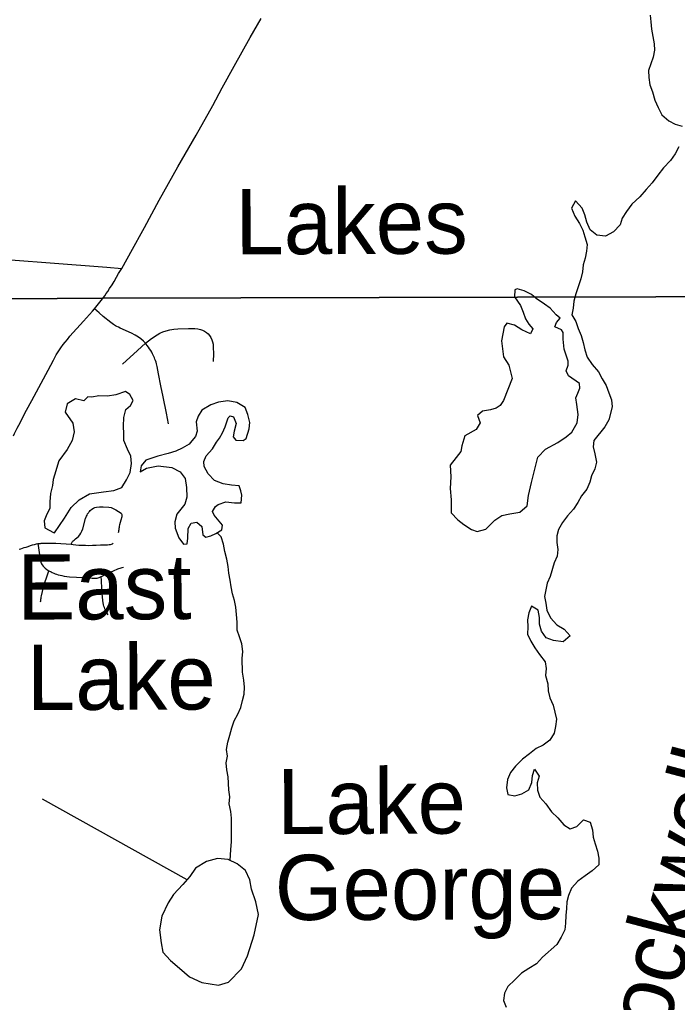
# Model space of a CAD drawing. Extents: x 0 to 34, y 0 to 22.
# Drawn here: x 3.606 to 4.562, y 16.187 to 17.616 of the extents above; entities that cross this region are included whole.
import ezdxf

# ---------------------------------------------------------------- set-up
doc = ezdxf.new("R2010")
doc.units = 0
for name, color, linetype in [('GM_X_City_Street', 7, 'Continuous'), ('GM_X_Corporation', 7, 'Continuous'), ('GM_X_County_Road', 7, 'Continuous'), ('GM_X_Major_Lake', 7, 'Continuous'), ('GM_X_Major_Lake_Text', 7, 'Continuous'), ('GM_X_Minor_Lake', 7, 'Continuous'), ('GM_X_Minor_Lake_Text', 7, 'Continuous'), ('GM_X_Minor_River', 7, 'Continuous'), ('GM_X_Township_Road', 7, 'Continuous')]:
    doc.layers.add(name, color=color, linetype=linetype)

msp = doc.modelspace()

# ---------------------------------------------------------------- linework, layer by layer
at = {"layer": 'GM_X_City_Street'}
msp.add_lwpolyline([(3.4853, 17.2733), (3.5792, 17.2674), (3.5989, 17.2659), (3.6499, 17.2621), (3.7323, 17.2558), (3.7541, 17.2539)], dxfattribs=at)
at = {"layer": 'GM_X_Corporation'}
for points in [[(2.114, 20.6173), (2.114, 17.2048), (2.159, 17.2055), (2.5952, 17.2097), (2.6493, 17.2102), (3.0597, 17.2067), (3.4848, 17.2088), (3.5941, 17.2097), (3.7259, 17.2107), (4.732, 17.2135)], [(4.732, 17.2135), (3.7259, 17.2107), (3.5941, 17.2097), (3.4848, 17.2088), (3.0597, 17.2067), (2.6493, 17.2102), (2.5952, 17.2097), (2.159, 17.2055), (2.114, 17.2048), (2.114, 13.8173), (5.0539, 13.8173)], [(3.5941, 17.2097), (3.7259, 17.2107), (4.732, 17.2135)]]:
    msp.add_lwpolyline(points, dxfattribs=at)
at = {"layer": 'GM_X_County_Road'}
for points in [[(3.7846, 17.3093), (3.787, 17.3137), (3.8087, 17.3535), (3.8221, 17.3773), (3.8358, 17.4017), (3.8626, 17.4479), (3.8864, 17.4908), (3.9002, 17.5165), (3.9176, 17.548), (3.941, 17.5897), (3.9567, 17.6173)], [(3.7541, 17.2539), (3.7698, 17.282), (3.7846, 17.3093)], [(3.7261, 17.2101), (3.7293, 17.2144), (3.7316, 17.2176), (3.7338, 17.2207), (3.7364, 17.2247), (3.7401, 17.2303), (3.743, 17.2352), (3.7466, 17.2412), (3.7496, 17.2466), (3.7541, 17.2539)], [(3.7144, 17.1954), (3.7185, 17.2003), (3.7224, 17.2051), (3.7261, 17.2101)], [(3.5966, 17.011), (3.5982, 17.0143), (3.6001, 17.018), (3.602, 17.0219), (3.6044, 17.0265), (3.6156, 17.048), (3.6233, 17.0622), (3.6301, 17.0748), (3.6469, 17.106), (3.6546, 17.1209), (3.6566, 17.1246), (3.6588, 17.1286), (3.6606, 17.1315), (3.6625, 17.1344), (3.6655, 17.1385), (3.6691, 17.1434), (3.6717, 17.1467), (3.6751, 17.151), (3.6786, 17.1555), (3.6985, 17.1774), (3.7116, 17.1921), (3.7144, 17.1954)]]:
    msp.add_lwpolyline(points, dxfattribs=at)
at = {"layer": 'GM_X_Major_Lake'}
for points in [[(4.5229, 17.6222), (4.5237, 17.6124), (4.5245, 17.6017), (4.5285, 17.5805), (4.5289, 17.5711), (4.5271, 17.5612), (4.5238, 17.5513), (4.5205, 17.5418), (4.5206, 17.5316), (4.5225, 17.5209), (4.526, 17.5107), (4.5295, 17.4986), (4.5345, 17.488), (4.5399, 17.4775), (4.5498, 17.4688), (4.5593, 17.464), (4.5692, 17.461)], [(4.5645, 17.4306), (4.5593, 17.4207), (4.5521, 17.4112), (4.542, 17.4001), (4.5341, 17.3898), (4.5259, 17.3784), (4.5169, 17.3688), (4.5079, 17.3581), (4.4962, 17.3474), (4.4884, 17.3367), (4.482, 17.3272), (4.4791, 17.3173), (4.4693, 17.3074), (4.4576, 17.3009), (4.4451, 17.3023), (4.4356, 17.3102), (4.4306, 17.3215), (4.4279, 17.3321), (4.4236, 17.3419), (4.4141, 17.3525), (4.4081, 17.3418), (4.4131, 17.3301), (4.42, 17.3195), (4.4246, 17.3097), (4.4277, 17.2999), (4.4309, 17.2889), (4.4302, 17.279), (4.4284, 17.2692), (4.4254, 17.2593), (4.4243, 17.249), (4.4218, 17.2388), (4.4185, 17.2289), (4.4144, 17.2171), (4.4118, 17.2065), (4.4108, 17.1962), (4.4089, 17.1867), (4.4147, 17.1769), (4.4182, 17.1667), (4.4224, 17.1565), (4.4252, 17.1466), (4.4279, 17.136), (4.431, 17.1251), (4.4383, 17.1145), (4.4474, 17.1036), (4.4528, 17.0938), (4.4589, 17.0839), (4.4624, 17.0734), (4.4667, 17.0632), (4.4675, 17.0529), (4.4624, 17.0339), (4.4568, 17.024), (4.441, 17.0042), (4.4396, 16.9947), (4.4423, 16.9845), (4.4447, 16.9727), (4.4421, 16.9628), (4.4373, 16.9529), (4.4351, 16.9434), (4.4306, 16.9332), (4.4227, 16.9236), (4.4175, 16.9141), (4.4111, 16.9042), (4.4025, 16.8947), (4.3954, 16.8847), (4.3894, 16.8748), (4.3869, 16.8653), (4.3869, 16.8559), (4.3885, 16.8456), (4.3875, 16.8361)], [(4.3875, 16.8361), (4.383, 16.8262), (4.3771, 16.8065), (4.373, 16.7966), (4.3708, 16.7871), (4.369, 16.7772), (4.371, 16.7674), (4.3726, 16.7572), (4.3779, 16.7462), (4.3871, 16.736), (4.3978, 16.73), (4.4062, 16.7199), (4.396, 16.7114)], [(4.396, 16.7114), (4.382, 16.7132), (4.3717, 16.7173), (4.3648, 16.7271), (4.3617, 16.737), (4.3617, 16.7468), (4.3597, 16.7574), (4.3502, 16.763), (4.3465, 16.7535), (4.3443, 16.7433), (4.3447, 16.733), (4.3445, 16.7224), (4.3491, 16.7126), (4.3548, 16.7028), (4.3617, 16.693), (4.3701, 16.6824), (4.3717, 16.6726), (4.3703, 16.6623), (4.3738, 16.6506), (4.3742, 16.6404), (4.377, 16.6298), (4.3816, 16.6192), (4.3843, 16.6094), (4.3867, 16.5988), (4.3852, 16.5885), (4.383, 16.5786), (4.3767, 16.5683), (4.3669, 16.5611), (4.3571, 16.5564), (4.3473, 16.5488), (4.3372, 16.5411), (4.327, 16.5308), (4.3195, 16.5213), (4.3151, 16.5114), (4.314, 16.4992), (4.3156, 16.4894), (4.3259, 16.4876), (4.3361, 16.4903), (4.3462, 16.4964), (4.3507, 16.5071), (4.3517, 16.517), (4.3547, 16.5265), (4.3612, 16.5163), (4.3583, 16.5064), (4.3587, 16.4958), (4.3622, 16.4856), (4.371, 16.4758), (4.379, 16.4641), (4.3886, 16.4554), (4.397, 16.4456), (4.4065, 16.4396), (4.4163, 16.4431), (4.426, 16.4527), (4.4355, 16.4493), (4.439, 16.4384), (4.4399, 16.4274), (4.4426, 16.4176), (4.4461, 16.4073), (4.4481, 16.3971), (4.4481, 16.3873), (4.4384, 16.3785), (4.4282, 16.3712), (4.4177, 16.3635), (4.4083, 16.3536), (4.4042, 16.3429), (4.4016, 16.3334), (4.4009, 16.3239), (4.4003, 16.3137), (4.3996, 16.3027), (4.3985, 16.2928), (4.3933, 16.2822), (4.387, 16.2715), (4.3659, 16.2531), (4.3573, 16.2432), (4.3464, 16.2367), (4.3358, 16.2298), (4.3261, 16.2202), (4.3159, 16.2107), (4.3111, 16.2008), (4.3093, 16.1901), (4.3131, 16.1803)]]:
    msp.add_lwpolyline(points, dxfattribs=at)
at = {"layer": 'GM_X_Minor_Lake'}
for p, q in [((4.3219, 17.0939), (4.3096, 17.0623)), ((3.8625, 17.0312), (3.8638, 17.0175)), ((3.6627, 16.9746), (3.6561, 16.9537)), ((3.8218, 16.332), (3.8125, 16.3129))]:
    msp.add_line(p, q, dxfattribs=at)
for points in [[(4.3096, 17.0623), (4.3048, 17.0551), (4.2987, 17.0508), (4.2904, 17.0485), (4.2791, 17.0465), (4.2716, 17.0404), (4.2754, 17.0298), (4.2695, 17.0199), (4.2533, 17.0107), (4.2488, 16.9962), (4.2474, 16.9879), (4.2406, 16.9795), (4.232, 16.9684), (4.2329, 16.9514), (4.2319, 16.9343), (4.2335, 16.918), (4.2333, 16.8987), (4.2432, 16.8889), (4.2516, 16.8821), (4.263, 16.8746), (4.271, 16.8716), (4.2835, 16.8752), (4.2966, 16.8881), (4.3068, 16.8951), (4.3185, 16.8974), (4.3332, 16.8998), (4.3437, 16.909), (4.3459, 16.9242), (4.3499, 16.9428), (4.3595, 16.9796), (4.3707, 16.9915), (4.3884, 17.0011), (4.4005, 17.0095), (4.4088, 17.0161), (4.4166, 17.0298), (4.418, 17.0419), (4.416, 17.0563), (4.4148, 17.0662), (4.4174, 17.0726), (4.4204, 17.0799), (4.4199, 17.0867), (4.404, 17.0979), (4.4005, 17.1051), (4.4035, 17.1135), (4.4034, 17.1192), (4.3976, 17.1369), (4.3963, 17.1513), (4.3963, 17.1608), (4.3936, 17.165), (4.3841, 17.1691), (4.3863, 17.1755), (4.3916, 17.182), (4.3862, 17.1865), (4.3771, 17.1963), (4.3691, 17.2023), (4.3569, 17.2106), (4.3501, 17.2162), (4.3394, 17.2214), (4.3292, 17.2244), (4.3258, 17.2229), (4.3255, 17.2126), (4.3343, 17.2002), (4.3381, 17.1903), (4.3412, 17.1809), (4.3462, 17.173), (4.3523, 17.1662), (4.3486, 17.1589), (4.3361, 17.1649), (4.3254, 17.1717), (4.3144, 17.1746), (4.3103, 17.1693), (4.3067, 17.1488), (4.3095, 17.1256), (4.3172, 17.1136), (4.3219, 17.0939)], [(3.6561, 16.9537), (3.6543, 16.9472), (3.6532, 16.9385), (3.6506, 16.9271), (3.6496, 16.915), (3.6493, 16.9055), (3.6444, 16.8945), (3.6415, 16.8872), (3.6423, 16.877), (3.6549, 16.8703), (3.6564, 16.8699), (3.671, 16.8913), (3.6803, 16.9065), (3.6923, 16.9176), (3.7074, 16.9264), (3.7278, 16.9292), (3.7426, 16.9312), (3.7543, 16.9359), (3.761, 16.9469), (3.7662, 16.9576), (3.7684, 16.9705), (3.7675, 16.9811), (3.7625, 16.9913), (3.7571, 17.0038), (3.7571, 17.0136), (3.7566, 17.025), (3.7572, 17.0375), (3.7602, 17.0489), (3.767, 17.0551), (3.7707, 17.0623), (3.7657, 17.071), (3.7596, 17.0751), (3.7456, 17.0704), (3.7332, 17.0685), (3.7207, 17.0687), (3.7105, 17.0668), (3.7048, 17.0675), (3.6988, 17.0617), (3.6866, 17.0647), (3.6746, 17.0574), (3.672, 17.0452), (3.6831, 17.0294), (3.6851, 17.0165), (3.6818, 17.004), (3.6747, 16.991), (3.6627, 16.9746)], [(3.8638, 17.0175), (3.8615, 17.0099), (3.8563, 17.0034), (3.8522, 16.9988), (3.842, 16.9931), (3.8326, 16.9884), (3.8216, 16.9853), (3.8065, 16.9814), (3.7891, 16.9752), (3.7824, 16.9672), (3.781, 16.9585), (3.79, 16.9638), (3.807, 16.967), (3.8271, 16.9649), (3.8389, 16.9585), (3.8465, 16.9487), (3.8485, 16.9359), (3.8486, 16.9218), (3.8457, 16.9116), (3.834, 16.8971), (3.8315, 16.8857), (3.8316, 16.8766), (3.8373, 16.8626), (3.8438, 16.8535), (3.8491, 16.8536), (3.8502, 16.8623), (3.8505, 16.8763), (3.855, 16.884), (3.8633, 16.8852), (3.8705, 16.8788), (3.8721, 16.867), (3.8763, 16.8633), (3.8835, 16.8656), (3.891, 16.8687), (3.8997, 16.8741), (3.9008, 16.8809), (3.8935, 16.8899), (3.8886, 16.8956), (3.8862, 16.9009), (3.8907, 16.9081), (3.8945, 16.9112), (3.9054, 16.9151), (3.9183, 16.9133), (3.9278, 16.9133), (3.9288, 16.9244), (3.9273, 16.9308), (3.9249, 16.938), (3.9139, 16.939), (3.9014, 16.9408), (3.8889, 16.946), (3.8798, 16.9554), (3.874, 16.9664), (3.8736, 16.9736), (3.8769, 16.9816), (3.8859, 16.9919), (3.8919, 17.0018), (3.8964, 17.0075), (3.9009, 17.0151), (3.9046, 17.0239), (3.909, 17.0368), (3.9116, 17.0399), (3.9166, 17.0384), (3.9204, 17.0289), (3.9175, 17.0176), (3.9164, 17.0092), (3.9202, 17.0043), (3.9305, 17.004), (3.935, 17.0071), (3.9394, 17.0211), (3.9405, 17.0302), (3.9377, 17.042), (3.9335, 17.0518), (3.9217, 17.0593), (3.9085, 17.0615), (3.8948, 17.0595), (3.8839, 17.056), (3.8707, 17.0483), (3.8655, 17.0395), (3.8625, 17.0312)], [(3.8125, 16.3129), (3.8092, 16.2928), (3.8113, 16.2739), (3.814, 16.2606), (3.8251, 16.2482), (3.8381, 16.2369), (3.8529, 16.2245), (3.8704, 16.2163), (3.8947, 16.2123), (3.9094, 16.2166), (3.9285, 16.2361), (3.9371, 16.2551), (3.9467, 16.2855), (3.9529, 16.3152), (3.949, 16.3337), (3.9428, 16.3519), (3.9404, 16.3655), (3.9342, 16.3791), (3.922, 16.3889), (3.9087, 16.3952), (3.8932, 16.3966), (3.8774, 16.3923), (3.8615, 16.3827), (3.8533, 16.3705), (3.8428, 16.3587), (3.8293, 16.3442), (3.8218, 16.332)]]:
    msp.add_lwpolyline(points, dxfattribs=at)
at = {"layer": 'GM_X_Minor_River'}
for points in [[(3.9117, 16.3938), (3.9128, 16.4096), (3.9138, 16.4207), (3.9137, 16.4343), (3.914, 16.4449), (3.914, 16.4552), (3.9127, 16.465), (3.9104, 16.476), (3.9114, 16.4862), (3.9098, 16.4965), (3.9089, 16.5154), (3.907, 16.5256), (3.9058, 16.5355), (3.9079, 16.545), (3.9067, 16.5548), (3.9082, 16.5655), (3.9111, 16.5757), (3.9141, 16.5864), (3.9174, 16.5966), (3.923, 16.6062), (3.9271, 16.616), (3.93, 16.6259), (3.9322, 16.6354), (3.9325, 16.6453), (3.9317, 16.6559), (3.9297, 16.6673), (3.9295, 16.687), (3.9302, 16.6972), (3.9286, 16.7086), (3.9255, 16.7188), (3.922, 16.7286), (3.9219, 16.74), (3.9211, 16.751), (3.9203, 16.7616), (3.9179, 16.7714), (3.9152, 16.7813), (3.9132, 16.7911), (3.912, 16.801), (3.91, 16.8112), (3.9088, 16.8211), (3.9068, 16.8317), (3.9041, 16.8426), (3.9021, 16.8532), (3.8986, 16.8638), (3.8927, 16.8697)], [(3.8491, 16.3657), (3.6386, 16.4826)]]:
    msp.add_lwpolyline(points, dxfattribs=at)
at = {"layer": 'GM_X_Township_Road'}
for points in [[(3.7885, 17.1453), (3.7875, 17.1463), (3.7857, 17.1482), (3.7819, 17.1516), (3.7784, 17.1543), (3.7736, 17.1573), (3.7685, 17.1599), (3.752, 17.1672), (3.7495, 17.1685), (3.7471, 17.1697), (3.745, 17.1709), (3.7423, 17.1725), (3.7383, 17.1753), (3.7272, 17.1843), (3.7211, 17.1895), (3.7144, 17.1954)], [(3.7885, 17.1453), (3.7976, 17.1522), (3.8057, 17.1576), (3.8095, 17.1598), (3.8141, 17.1619), (3.8188, 17.1636), (3.8243, 17.165), (3.8299, 17.166), (3.8355, 17.1665), (3.8511, 17.1667), (3.8604, 17.1668), (3.8649, 17.1663), (3.8686, 17.1655), (3.8716, 17.1644), (3.8745, 17.1629), (3.8772, 17.1611), (3.8796, 17.159), (3.8817, 17.1565), (3.8835, 17.1539), (3.8853, 17.1504), (3.8863, 17.1474), (3.887, 17.1442), (3.8873, 17.1398), (3.8875, 17.1298), (3.8871, 17.1186)], [(3.7552, 17.1152), (3.777, 17.1346), (3.7885, 17.1453)], [(3.8221, 17.0283), (3.819, 17.0436), (3.8143, 17.0676), (3.811, 17.0834), (3.8078, 17.101), (3.8058, 17.1117), (3.8049, 17.1153), (3.8042, 17.1178), (3.8033, 17.1201), (3.8024, 17.1223), (3.8016, 17.1243), (3.8004, 17.127), (3.7989, 17.1301), (3.7977, 17.1323), (3.7962, 17.135), (3.7947, 17.1373), (3.7931, 17.1397), (3.7913, 17.1419), (3.7896, 17.1441), (3.7885, 17.1453)], [(3.6803, 16.8532), (3.6813, 16.8555), (3.6825, 16.8572), (3.6836, 16.8582), (3.6847, 16.8594), (3.6869, 16.8611), (3.6889, 16.8624), (3.6911, 16.8644), (3.6932, 16.8667), (3.6948, 16.8693), (3.6962, 16.8721), (3.6974, 16.8756), (3.7015, 16.8906), (3.7028, 16.8941), (3.7037, 16.8957), (3.7045, 16.8974), (3.7056, 16.8989), (3.7063, 16.8999), (3.7073, 16.901), (3.7084, 16.9022), (3.7108, 16.9043), (3.7128, 16.9056), (3.7151, 16.9065), (3.7175, 16.9071), (3.7218, 16.9076), (3.7272, 16.9075), (3.7354, 16.907), (3.7385, 16.9064), (3.7414, 16.9053), (3.7434, 16.9043), (3.7453, 16.9033), (3.7531, 16.8984), (3.7539, 16.8974), (3.7543, 16.8963), (3.7543, 16.895), (3.754, 16.8932), (3.7526, 16.8884), (3.7507, 16.8813), (3.7504, 16.8793), (3.7502, 16.8777), (3.75, 16.8759), (3.7498, 16.8741), (3.7495, 16.8726), (3.7492, 16.8711), (3.749, 16.8699)], [(3.605, 16.8462), (3.6075, 16.8466), (3.6098, 16.8474), (3.6124, 16.8483), (3.6152, 16.8492), (3.6179, 16.8501), (3.6215, 16.8513), (3.6244, 16.8522), (3.6273, 16.853), (3.6301, 16.8536), (3.6322, 16.8541), (3.6357, 16.8545), (3.6371, 16.8547), (3.6399, 16.8549), (3.6421, 16.855), (3.6582, 16.8547), (3.6803, 16.8532), (3.6835, 16.8528), (3.6872, 16.8524), (3.6919, 16.852), (3.6968, 16.8517), (3.7016, 16.8517), (3.7061, 16.8516), (3.7114, 16.8519), (3.7167, 16.8521), (3.7234, 16.8525), (3.7289, 16.8525), (3.7333, 16.8525), (3.7357, 16.8527), (3.7376, 16.853), (3.7393, 16.8534), (3.7405, 16.8539), (3.7415, 16.8546)], [(3.6322, 16.8541), (3.633, 16.848), (3.6348, 16.8345), (3.6352, 16.8321), (3.6358, 16.8296), (3.6365, 16.8271), (3.6373, 16.8249), (3.6382, 16.8233), (3.6397, 16.8214), (3.6408, 16.8203), (3.6427, 16.8185), (3.6452, 16.8166), (3.6481, 16.8148), (3.6513, 16.8131), (3.6531, 16.8121), (3.6552, 16.8112), (3.6573, 16.8103), (3.6593, 16.8096), (3.6617, 16.8088), (3.6645, 16.8082), (3.6672, 16.8076), (3.6704, 16.807), (3.6742, 16.8065), (3.6783, 16.8061), (3.6987, 16.8048), (3.7111, 16.804), (3.7137, 16.8039), (3.716, 16.8038), (3.7185, 16.804), (3.72, 16.8044), (3.7215, 16.805), (3.7243, 16.8063), (3.7257, 16.807), (3.73, 16.8091), (3.7422, 16.8145), (3.7485, 16.8173), (3.7532, 16.819), (3.7547, 16.8194), (3.7568, 16.8199)], [(3.6361, 16.7695), (3.6362, 16.7709), (3.6363, 16.772), (3.6366, 16.7736), (3.6368, 16.775), (3.637, 16.7765), (3.6372, 16.7781), (3.6387, 16.7847), (3.6415, 16.7947), (3.6461, 16.8087), (3.6481, 16.8148)], [(3.7342, 16.7507), (3.7334, 16.7519), (3.7324, 16.7534), (3.7315, 16.7552), (3.7304, 16.7576), (3.7296, 16.7593), (3.7288, 16.7612), (3.7281, 16.7633), (3.7276, 16.7653), (3.7266, 16.7713), (3.7254, 16.7817), (3.725, 16.7888), (3.7245, 16.8007), (3.7243, 16.8063)]]:
    msp.add_lwpolyline(points, dxfattribs=at)

# ---------------------------------------------------------------- texts
at = {"layer": 'GM_X_Major_Lake_Text'}
msp.add_text('Rockwell', height=0.09473, rotation=75.1742, dxfattribs=at).set_placement((4.5237, 16.052))
at = {"layer": 'GM_X_Minor_Lake_Text'}
for s, rotation, p in [('Lakes', 0.1742, (3.9194, 17.2746)), ('East', 0.1739, (3.6021, 16.7437)), ('Lake', 0.1741, (3.6162, 16.6123)), ('Lake', 0.1739, (3.9802, 16.4319)), ('George', 0.1732, (3.9768, 16.307))]:
    msp.add_text(s, height=0.09474, rotation=rotation, dxfattribs=at).set_placement(p)

doc.saveas('drawing.dxf')
